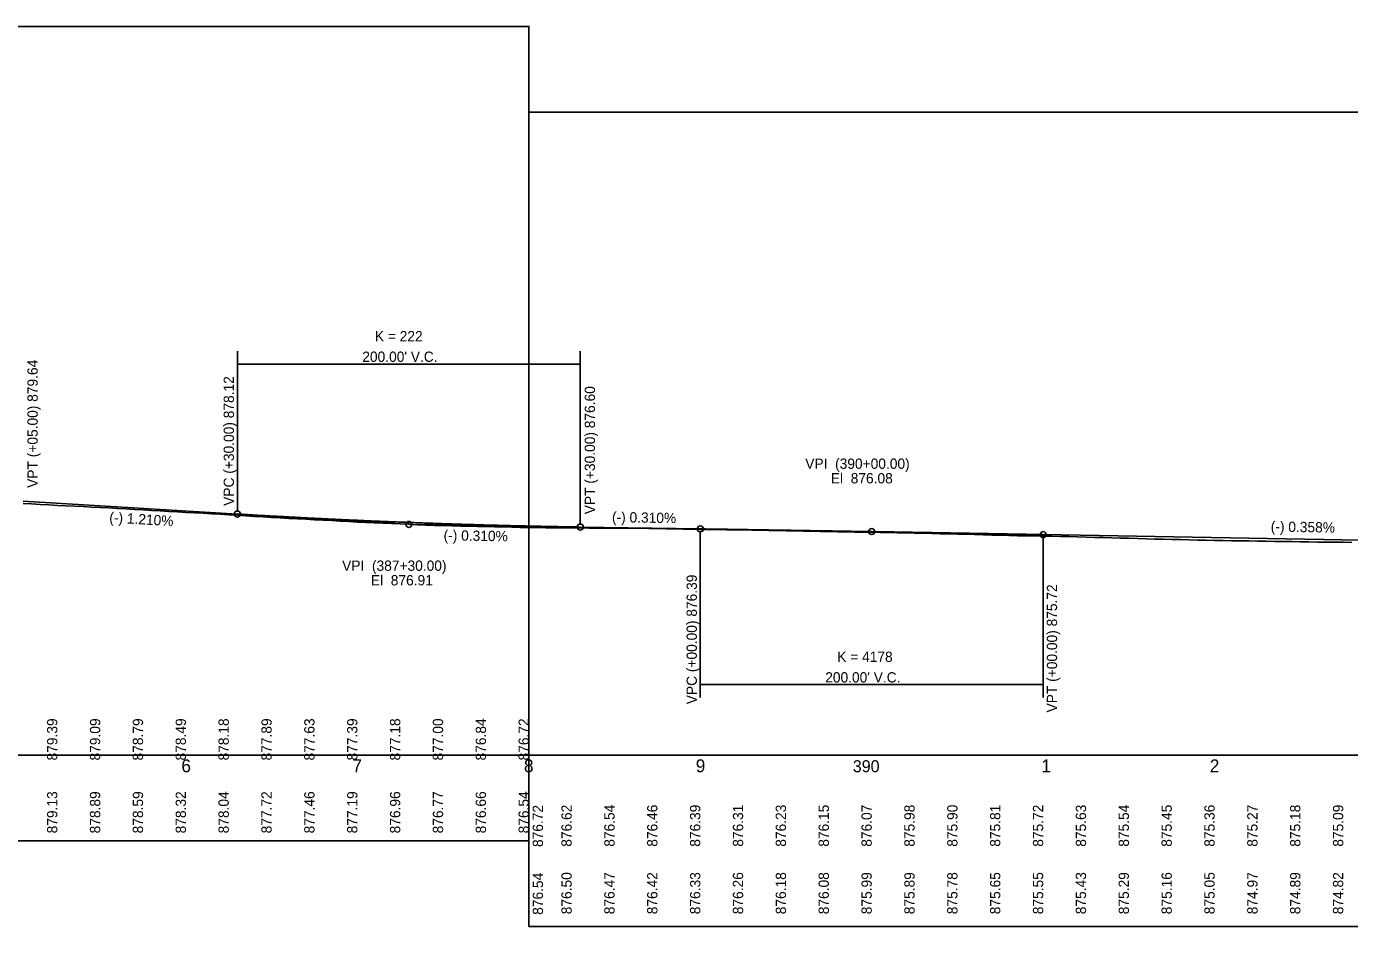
# Model space of a CAD drawing. Extents: x 4180 to 16997695, y 4 to 12629821.
# Drawn here: x 16990927 to 16991699, y 12628362 to 12628887 of the extents above; entities that cross this region are included whole.
import ezdxf

# ---------------------------------------------------------------- set-up
doc = ezdxf.new("R2010")
doc.units = 0
for name, color, linetype in [('Default', 7, 'Continuous'), ('RD_DDB_GradeTX', 7, 'Continuous'), ('RD_DDB_PI', 7, 'Continuous'), ('RD_DDB_Profile_EX', 7, 'Continuous'), ('RD_DDB_Profile_PR', 7, 'Continuous'), ('RD_DDB_StaTX', 7, 'Continuous'), ('RD_DDB_StripGrade', 7, 'Continuous'), ('RD_DDB_StripGrade_PR', 7, 'Continuous'), ('RD_DDB_VCLbl', 7, 'Continuous'), ('RD_GPK_Profile_Cell', 7, 'Continuous')]:
    doc.layers.add(name, color=color, linetype=linetype)

msp = doc.modelspace()

# ---------------------------------------------------------------- linework, layer by layer
at = {"layer": 'Default'}
for points in [[(16989719.88, 12628411.61), (16991219.88, 12628411.61), (16991219.88, 12628886.61), (16989719.88, 12628886.61)], [(16991219.88, 12628361.61), (16992719.88, 12628361.61), (16992719.88, 12628836.61), (16991219.88, 12628836.61)]]:
    msp.add_lwpolyline(points, close=True, dxfattribs=at)
at = {"layer": 'RD_DDB_PI'}
for p, q in [((16991060.04, 12628601.62), (16991148.13, 12628596.29)), ((16991239.86, 12628594.79), (16991151.62, 12628596.16)), ((16991329.89, 12628593.39), (16991418.13, 12628592.03)), ((16991509.86, 12628590.39), (16991421.62, 12628591.97))]:
    msp.add_line(p, q, dxfattribs=at)
for centre in [(16991149.88, 12628596.18), (16991419.88, 12628592)]:
    msp.add_circle(centre, 1.75, dxfattribs=at)
at = {"layer": 'RD_DDB_Profile_EX'}
for points in [[(16990924.88, 12628608.45), (16990929.88, 12628608.16), (16990934.88, 12628607.87), (16990939.88, 12628607.57), (16990944.88, 12628607.27), (16990949.88, 12628607.07), (16990954.88, 12628606.82), (16990959.88, 12628606.57), (16990964.88, 12628606.32), (16990969.88, 12628606.05), (16990974.88, 12628605.75), (16990979.88, 12628605.46), (16990984.88, 12628605.16), (16990989.88, 12628604.87), (16990994.88, 12628604.58), (16990999.88, 12628604.29), (16991004.88, 12628604), (16991009.88, 12628603.73), (16991014.88, 12628603.47), (16991019.88, 12628603.21), (16991024.88, 12628602.94), (16991029.88, 12628602.67), (16991034.88, 12628602.4), (16991039.88, 12628602.12), (16991044.88, 12628601.83), (16991049.88, 12628601.51), (16991054.88, 12628601.18), (16991059.88, 12628600.84), (16991064.88, 12628600.52), (16991069.88, 12628600.23), (16991074.88, 12628599.94), (16991079.88, 12628599.65), (16991084.88, 12628599.38), (16991089.88, 12628599.14), (16991094.88, 12628598.9), (16991099.88, 12628598.66), (16991104.88, 12628598.4), (16991109.88, 12628598.12), (16991114.88, 12628597.83), (16991119.88, 12628597.54), (16991124.88, 12628597.3), (16991129.88, 12628597.09), (16991134.88, 12628596.87), (16991139.88, 12628596.65), (16991144.88, 12628596.43), (16991149.88, 12628596.22), (16991154.88, 12628596), (16991159.88, 12628595.79), (16991164.88, 12628595.61), (16991169.88, 12628595.46)], [(16991169.88, 12628595.46), (16991174.88, 12628595.31), (16991179.88, 12628595.16), (16991184.88, 12628595.08), (16991189.88, 12628594.99), (16991194.88, 12628594.9), (16991199.88, 12628594.81), (16991204.88, 12628594.7), (16991209.88, 12628594.57), (16991214.88, 12628594.44), (16991219.88, 12628594.32), (16991224.88, 12628594.28), (16991229.88, 12628594.24), (16991234.88, 12628594.2), (16991239.88, 12628594.15), (16991244.88, 12628594.11), (16991249.88, 12628594.08), (16991254.88, 12628594.04), (16991259.88, 12628594.01), (16991264.88, 12628593.98), (16991269.88, 12628593.97), (16991274.88, 12628593.96), (16991279.88, 12628593.95), (16991284.88, 12628593.89), (16991289.88, 12628593.81), (16991294.88, 12628593.73), (16991299.88, 12628593.64), (16991304.88, 12628593.55), (16991309.88, 12628593.45), (16991314.88, 12628593.35), (16991319.88, 12628593.27), (16991324.88, 12628593.19), (16991329.88, 12628593.11), (16991334.88, 12628593.04), (16991339.88, 12628592.98), (16991344.88, 12628592.91), (16991349.88, 12628592.84), (16991354.88, 12628592.77), (16991359.88, 12628592.7), (16991364.88, 12628592.6), (16991369.88, 12628592.5), (16991374.88, 12628592.4), (16991379.88, 12628592.3), (16991384.88, 12628592.21), (16991389.88, 12628592.11), (16991394.88, 12628592), (16991399.88, 12628591.9), (16991404.88, 12628591.79), (16991409.88, 12628591.72), (16991414.88, 12628591.64), (16991419.88, 12628591.56), (16991424.88, 12628591.47), (16991429.88, 12628591.37), (16991434.88, 12628591.28), (16991439.88, 12628591.18), (16991444.88, 12628591.08), (16991449.88, 12628590.97), (16991454.88, 12628590.87), (16991459.88, 12628590.76), (16991464.88, 12628590.63), (16991469.88, 12628590.51), (16991474.88, 12628590.38), (16991479.88, 12628590.25), (16991484.88, 12628590.12), (16991489.88, 12628589.98), (16991494.88, 12628589.84), (16991499.88, 12628589.7), (16991504.88, 12628589.56), (16991509.88, 12628589.5), (16991514.88, 12628589.44), (16991519.88, 12628589.37), (16991524.88, 12628589.28), (16991529.88, 12628589.15), (16991534.88, 12628589.03), (16991539.88, 12628588.89), (16991544.88, 12628588.76), (16991549.88, 12628588.62), (16991554.88, 12628588.47), (16991559.88, 12628588.32), (16991564.88, 12628588.17), (16991569.88, 12628588.05), (16991574.88, 12628587.91), (16991579.88, 12628587.78), (16991584.88, 12628587.65), (16991589.88, 12628587.53), (16991594.88, 12628587.42), (16991599.88, 12628587.29), (16991604.88, 12628587.18), (16991609.88, 12628587.07), (16991614.88, 12628586.97), (16991619.88, 12628586.85), (16991624.88, 12628586.74), (16991629.88, 12628586.67), (16991634.88, 12628586.62), (16991639.88, 12628586.55), (16991644.88, 12628586.47), (16991649.88, 12628586.39), (16991654.88, 12628586.29), (16991659.88, 12628586.21), (16991664.88, 12628586.13), (16991669.88, 12628586.04)], [(16991669.88, 12628586.04), (16991674.88, 12628585.96), (16991679.88, 12628585.9), (16991684.88, 12628585.85), (16991689.88, 12628585.79), (16991694.88, 12628585.74), (16991699.88, 12628585.7)]]:
    msp.add_lwpolyline(points, dxfattribs=at)
at = {"layer": 'RD_DDB_Profile_PR'}
for p, q in [((16990924.88, 12628609.8), (16991049.88, 12628602.23)), ((16991249.88, 12628594.63), (16991319.88, 12628593.55)), ((16991519.88, 12628590.21), (16991789.88, 12628585.38))]:
    msp.add_line(p, q, dxfattribs=at)
for points in [[(16991049.88, 12628602.23), (16991053.88, 12628601.99), (16991057.88, 12628601.76), (16991061.88, 12628601.52), (16991065.88, 12628601.29), (16991069.88, 12628601.07), (16991073.88, 12628600.85), (16991077.88, 12628600.63), (16991081.88, 12628600.41), (16991085.88, 12628600.2), (16991089.88, 12628599.99), (16991093.88, 12628599.79), (16991097.88, 12628599.59), (16991101.88, 12628599.39), (16991105.88, 12628599.2), (16991109.88, 12628599.01), (16991113.88, 12628598.82), (16991117.88, 12628598.64), (16991121.88, 12628598.46), (16991125.88, 12628598.29), (16991129.88, 12628598.11), (16991133.88, 12628597.95), (16991137.88, 12628597.78), (16991141.88, 12628597.62), (16991145.88, 12628597.46), (16991149.88, 12628597.31), (16991153.88, 12628597.16), (16991157.88, 12628597.01), (16991161.88, 12628596.87), (16991165.88, 12628596.73), (16991169.88, 12628596.59), (16991173.88, 12628596.46), (16991177.88, 12628596.33), (16991181.88, 12628596.21), (16991185.88, 12628596.09), (16991189.88, 12628595.97), (16991193.88, 12628595.85), (16991197.88, 12628595.74), (16991201.88, 12628595.64), (16991205.88, 12628595.53), (16991209.88, 12628595.43), (16991213.88, 12628595.34), (16991217.88, 12628595.25), (16991221.88, 12628595.16), (16991225.88, 12628595.07), (16991229.88, 12628594.99), (16991233.88, 12628594.91), (16991237.88, 12628594.84), (16991241.88, 12628594.77), (16991245.88, 12628594.7), (16991249.88, 12628594.63)], [(16991319.88, 12628593.55), (16991323.88, 12628593.49), (16991327.88, 12628593.42), (16991331.88, 12628593.36), (16991335.88, 12628593.3), (16991339.88, 12628593.24), (16991343.88, 12628593.17), (16991347.88, 12628593.11), (16991351.88, 12628593.05), (16991355.88, 12628592.98), (16991359.88, 12628592.92), (16991363.88, 12628592.86), (16991367.88, 12628592.79), (16991371.88, 12628592.73), (16991375.88, 12628592.66), (16991379.88, 12628592.6), (16991383.88, 12628592.53), (16991387.88, 12628592.47), (16991391.88, 12628592.4), (16991395.88, 12628592.34), (16991399.88, 12628592.27), (16991403.88, 12628592.2), (16991407.88, 12628592.14), (16991411.88, 12628592.07), (16991415.88, 12628592.01), (16991419.88, 12628591.94), (16991423.88, 12628591.87), (16991427.88, 12628591.81), (16991431.88, 12628591.74), (16991435.88, 12628591.67), (16991439.88, 12628591.6), (16991443.88, 12628591.54), (16991447.88, 12628591.47), (16991451.88, 12628591.4), (16991455.88, 12628591.33), (16991459.88, 12628591.26), (16991463.88, 12628591.19), (16991467.88, 12628591.12), (16991471.88, 12628591.05), (16991475.88, 12628590.99), (16991479.88, 12628590.92), (16991483.88, 12628590.85), (16991487.88, 12628590.78), (16991491.88, 12628590.71), (16991495.88, 12628590.64), (16991499.88, 12628590.57), (16991503.88, 12628590.49), (16991507.88, 12628590.42), (16991511.88, 12628590.35), (16991515.88, 12628590.28), (16991519.88, 12628590.21)]]:
    msp.add_spline(points, degree=3, dxfattribs=at)
at = {"layer": 'RD_DDB_VCLbl'}
for p, q in [((16991049.88, 12628697.23), (16991049.88, 12628603.98)), ((16991249.88, 12628697.23), (16991249.88, 12628596.38)), ((16991049.88, 12628689.73), (16991249.88, 12628689.73)), ((16991319.88, 12628495.21), (16991319.88, 12628591.8)), ((16991519.88, 12628495.21), (16991519.88, 12628588.46)), ((16991319.88, 12628502.71), (16991519.88, 12628502.71))]:
    msp.add_line(p, q, dxfattribs=at)
for centre in [(16991049.88, 12628602.23), (16991249.88, 12628594.63), (16991319.88, 12628593.55), (16991519.88, 12628590.21)]:
    msp.add_circle(centre, 1.75, dxfattribs=at)
at = {"layer": 'RD_GPK_Profile_Cell'}
msp.add_line((16972619.88, 12628461.61), (16997196.51, 12628461.61), dxfattribs=at)

# ---------------------------------------------------------------- texts
at = {"layer": 'RD_DDB_GradeTX'}
for s, rotation, p in [('(-) 1.210%', 356.5378, (16990975.05, 12628597.34)), ('(-) 0.310%', 359.11198, (16991268.33, 12628597.46)), ('(-) 0.358%', 358.97488, (16991652.56, 12628591.99)), ('(-) 0.310%', 359.11198, (16991170.12, 12628586.87))]:
    msp.add_text(s, height=6, rotation=rotation, dxfattribs=at).set_placement(p)
at = {"layer": 'RD_DDB_PI'}
for s, p in [('VPI  (390+00.00)', (16991381.11, 12628628.59)), ('El  876.08', (16991396.02, 12628620.09)), ('VPI  (387+30.00)', (16991110.99, 12628569.1)), ('El  876.91', (16991127.76, 12628560.6))]:
    msp.add_text(s, height=6, dxfattribs=at).set_placement(p)
at = {"layer": 'RD_DDB_StaTX'}
for s, height, p in [('6', 7.5, (16991017.23, 12628451.61)), ('7', 7.5, (16991117, 12628451.61)), ('8', 7.5, (16991217.03, 12628451.61)), ('9', 7.5, (16991317.23, 12628451.61)), ('390', 7, (16991408.83, 12628451.61)), ('1', 7.5, (16991518.87, 12628451.61)), ('2', 7.5, (16991617.03, 12628451.61))]:
    msp.add_text(s, height=height, dxfattribs=at).set_placement(p)
at = {"layer": 'RD_DDB_StripGrade'}
for s, p in [('879.13', (16990944.88, 12628415.95)), ('878.89', (16990969.88, 12628415.95)), ('878.59', (16990994.88, 12628415.95)), ('878.32', (16991019.88, 12628415.95)), ('878.04', (16991044.88, 12628415.95)), ('877.72', (16991069.88, 12628415.95)), ('877.46', (16991094.88, 12628415.95)), ('877.19', (16991119.88, 12628415.95)), ('876.96', (16991144.88, 12628415.95)), ('876.77', (16991169.88, 12628415.95)), ('876.66', (16991194.88, 12628415.95)), ('876.54', (16991219.88, 12628415.95)), ('876.54', (16991228.15, 12628368.44)), ('876.50', (16991244.88, 12628368.78)), ('876.47', (16991269.88, 12628368.78)), ('876.42', (16991294.88, 12628368.78)), ('876.33', (16991319.88, 12628368.78)), ('876.26', (16991344.88, 12628368.78)), ('876.18', (16991369.88, 12628368.78)), ('876.08', (16991394.88, 12628368.78)), ('875.99', (16991419.88, 12628368.78)), ('875.89', (16991444.88, 12628368.78)), ('875.78', (16991469.88, 12628368.78)), ('875.65', (16991494.88, 12628368.78)), ('875.55', (16991519.88, 12628368.78)), ('875.43', (16991544.88, 12628368.78)), ('875.29', (16991569.88, 12628368.78)), ('875.16', (16991594.88, 12628368.78)), ('875.05', (16991619.88, 12628368.78)), ('874.97', (16991644.88, 12628368.78)), ('874.89', (16991669.88, 12628368.78)), ('874.82', (16991694.88, 12628368.78))]:
    msp.add_text(s, height=6, rotation=90, dxfattribs=at).set_placement(p)
at = {"layer": 'RD_DDB_StripGrade_PR'}
for s, p in [('879.39', (16990944.88, 12628458.48)), ('879.09', (16990969.88, 12628458.48)), ('878.79', (16990994.88, 12628458.48)), ('878.49', (16991019.88, 12628458.48)), ('878.18', (16991044.88, 12628458.48)), ('877.89', (16991069.88, 12628458.48)), ('877.63', (16991094.88, 12628458.48)), ('877.39', (16991119.88, 12628458.48)), ('877.18', (16991144.88, 12628458.48)), ('877.00', (16991169.88, 12628458.48)), ('876.84', (16991194.88, 12628458.48)), ('876.72', (16991219.88, 12628458.48)), ('876.72', (16991228.11, 12628407.99)), ('876.62', (16991244.88, 12628408.16)), ('876.54', (16991269.88, 12628408.16)), ('876.46', (16991294.88, 12628408.16)), ('876.39', (16991319.88, 12628408.16)), ('876.31', (16991344.88, 12628408.16)), ('876.23', (16991369.88, 12628408.16)), ('876.15', (16991394.88, 12628408.16)), ('876.07', (16991419.88, 12628408.16)), ('875.98', (16991444.88, 12628408.16)), ('875.90', (16991469.88, 12628408.16)), ('875.81', (16991494.88, 12628408.16)), ('875.72', (16991519.88, 12628408.16)), ('875.63', (16991544.88, 12628408.16)), ('875.54', (16991569.88, 12628408.16)), ('875.45', (16991594.88, 12628408.16)), ('875.36', (16991619.88, 12628408.16)), ('875.27', (16991644.88, 12628408.16)), ('875.18', (16991669.88, 12628408.16)), ('875.09', (16991694.88, 12628408.16))]:
    msp.add_text(s, height=6, rotation=90, dxfattribs=at).set_placement(p)
at = {"layer": 'RD_DDB_VCLbl'}
for s, p in [('K = 222', (16991130.07, 12628702.98)), ("200.00' V.C.", (16991122.74, 12628690.98)), ('K = 4178', (16991399.74, 12628515.96)), ("200.00' V.C.", (16991392.74, 12628503.96))]:
    msp.add_text(s, height=6, dxfattribs=at).set_placement(p)
for s, p in [('VPT (+05.00) 879.64', (16990933.43, 12628617.5)), ('VPC (+30.00) 878.12', (16991047.88, 12628607.01)), ('VPT (+30.00) 876.60', (16991258.47, 12628602.1)), ('VPC (+00.00) 876.39', (16991317.88, 12628491.28)), ('VPT (+00.00) 875.72', (16991527.98, 12628486.5))]:
    msp.add_text(s, height=6, rotation=90, dxfattribs=at).set_placement(p)

doc.saveas('drawing.dxf')
